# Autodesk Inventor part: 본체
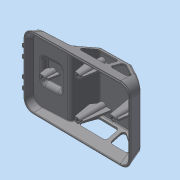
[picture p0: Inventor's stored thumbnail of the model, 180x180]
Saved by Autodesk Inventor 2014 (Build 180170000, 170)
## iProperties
Created: 2015-05
Part Number: 본체
Material: 일반
Document SubType Name: Modeling
Designer: dgall
Density: 1 g/cm^3
Appearance: 기본값
Author: dgall
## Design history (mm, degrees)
sketch "스케치1"
  geometry: L1 (-61, 0)-(61, 0); L2 (-61, 0)-(-61, 9); L3 (-61, 0)-(-58.588, 9); L4 (-61, 9)-(-19, 9); L5 (61, 0)-(31, 0); L6 (31, 0)-(31, 31); L7 (31, 31)-(57.056, 14.718); L8 (61, 0)-(57.056, 14.718); L9 (31, 31)-(-4.605, 31); L10 (-60, -1)-(60, -1); L11 (60, -1)-(60, 0); L12 (-61, 0)-(-60, 0); L13 (-60, 0)-(-60, -1); L14 (-4.605, 31)-(-18.633, 11.094); L15 (-58.588, 9)-(-18.633, 11.094); 2 further points
  constraints: 30 end point, 5 perpendicular, 4 point on line, 1 coincident, 1 horizontal, 1 midpoint, 1 parallel
  dimensions: "d0" = 122 distance of L1.start L1.end; "d3" = 9 distance of L1.start L2.end; "d4" = 75 deg angle of L1 L3; "d6" = 42 distance of L2.end L4.end; "d9" = 30 distance of L1.end L5.end; "d10" = 31 distance of L5.end L6.end; "d12" = 105 deg angle of L1 L8; "d13" = 35.60485 distance of L6.end L9.end; "d16" = 1 distance of L10.end L11.end; "d17" = 1 distance of L1.end L11.end; "d18" = 1 distance of L1.start L12.end; "d19" = 1 distance of L10.start L12.end; "d23" = 24.35241 distance of L9.end L14.end; "d24" = 30.72498 distance of L6.end L7.end; "d25" = 3 deg angle of L4 L15
extrude "돌출2" new body sketch "스케치1" stored distance "d26" = 76; taper "d27" = 0 deg
sketch "스케치2"
  geometry: L1 (0, 76)-(0, 0) reference; L2 (58.037, 38)-(0, 38); L3 (0, 38)-(11, 38); L4 (11, 51)-(11, 25); L5 (11, 51)-(31, 51); L6 (31, 51)-(31, 25); L7 (31, 25)-(11, 25)
  constraints: 12 end point, 3 perpendicular, 2 midpoint, 1 horizontal alignment, 1 point on line
  dimensions: "d29" = 26 distance of L4.start L4.end; "d30" = 11 distance of L2.end L3.end; "d31" = 20 distance of L4.start L5.end; "d32" = 26 distance of L5.end L6.end
extrude "돌출3" join sketch "스케치2" distance "d33" = 5; taper "d34" = 0 deg
fillet "모깎기1" dims "d72" = 3
fillet "모깎기2" dims "d73" = 2.5
sketch "스케치7"
  geometry: L1 (61.661, 76)-(61.661, 0) reference; L2 (65.605, 0)-(61.661, 0) reference; L3 (65.605, 76)-(65.605, 0) reference; L4 (61.661, 76)-(65.605, 76) reference; 3 further points
  constraints: 1 horizontal alignment, 1 midpoint, 1 other
  dimensions: "d74" = 50 distance from line of L3 point (15.605, 38)
  node "투영된 루프3"
feature "면 기울기3" dims angle "d139" = 15 deg
feature "면 기울기4" dims angle "d140" = 15 deg
fillet "모깎기7" dims "d141" = 12
fillet "모깎기8" dims "d142" = 3
fillet "모깎기9" dims "d143" = 2.5
feature "쉘2" dims "d144" = 2
sketch "스케치26"
  geometry: L1 (-3.049, 31)-(30.14, 31) reference; L2 (-17.793, 12.285)-(-5.501, 29.728) reference; L3 (31.73, 30.544)-(45.466, 21.961) reference; L4 (45.466, 21.961)-(56.054, 15.344) reference; L5 (-0.456, 26)-(18.418, 26); L6 (-2.908, 24.728)-(-9.25, 15.728); L7 (-6.798, 11)-(18.418, 11); L8 (21.418, 14)-(21.418, 23); L9 (25.571, 23)-(25.571, 14); L10 (30.296, 25.544)-(44.699, 16.544); L11 (28.571, 11)-(43.109, 11); L12 (28.571, 26)-(28.706, 26); A1 r 3 centre (18.418, 23) between (21.418, 23) and (18.418, 26); A2 r 3 centre (18.418, 14) between (18.418, 11) and (21.418, 14); A3 r 3 centre (-6.798, 14) between (-9.25, 15.728) and (-6.798, 11); A4 r 3 centre (28.571, 23) between (28.571, 26) and (25.571, 23); A5 r 3 centre (28.706, 23) between (30.296, 25.544) and (28.706, 26); A6 r 3 centre (28.571, 14) between (25.571, 14) and (28.571, 11); A7 r 3 centre (43.109, 14) between (43.109, 11) and (44.699, 16.544); A8 r 3 centre (-0.456, 23) between (-0.456, 26) and (-2.908, 24.728); 7 further points
  constraints: 16 end point, 16 point on circle, 16 tangent, 12 point on line, 8 centre point, 6 parallel, 5 equal radius, 2 perpendicular, 1 horizontal alignment
  dimensions: "d145" = 5 distance between parallel lines of L5 L1; "d147" = 5 distance between parallel lines of L2 L6; "d148" = 34 distance of point (-12.582, 11) point (21.418, 11); "d149" = 15 distance of point (21.418, 11) point (21.418, 26); "d150" = 3 radius of A1; "d151" = 5 distance between parallel lines of L10 L4; "d152" = 28 distance of point (25.571, 11) point (53.571, 11); "d153" = 15 distance of point (25.571, 26) point (25.571, 11); "d154" = 3 radius of A4; "d155" = 3 radius of A8
extrude "돌출12" cut sketch "스케치26" stored distance "d156" = 130; taper "d157" = 0 deg
feature "엠보싱2" dims "d158" = 0.5, "d159" = 0
sketch "스케치27"
  geometry: L1 (31, 30.583)-(31, -30.583) reference; L2 (29, 30.583)-(29, -30.583) reference; L3 (29, 22)-(29, -22); L4 (0, -28.811)-(0, 28.811) reference; L5 (29, 22)-(0, 22); L6 (29, -22)-(0, -22); L7 (0, 22)-(0, 25); L8 (0, 25)-(29, 26.013); L9 (29, 26.013)-(29, 22); L10 (0, -22)-(0, -25); L11 (0, -25)-(29, -26.013); L12 (29, -26.013)-(29, -22); 2 further points
  constraints: 18 end point, 6 point on line, 3 collinear, 2 midpoint, 2 perpendicular
  dimensions: "d160" = 44 distance of L3.start L3.end; "d161" = 3 distance of L5.end L7.end; "d162" = 2 deg angle of L5 L8; "d163" = 3 distance of L6.end L10.end; "d164" = 2 deg angle of L6 L11
revolve "회전3" stored, may be unused: angle "d165" = 90 deg
revolve "회전4" stored, may be unused: angle "d166" = 90 deg
sketch "스케치28"
  geometry: L1 (-44.765, 12.729)-(-30.784, 13.461) reference; L2 (-3.049, 29)-(-3.049, 29) reference; L3 (-3.866, 28.576)-(-3.866, 28.576) reference; L4 (-3, 0)-(3, 0) reference; L5 (0, 0)-(-40, 0); L6 (-40, 0)-(-40, 12.978); L7 (-40, 0)-(-37, 0); L8 (-37, 0)-(-36.54, 13.16); L9 (-36.54, 13.16)-(-40, 12.978)
  constraints: 10 end point, 3 point on line, 2 collinear, 1 perpendicular, 2 other
  dimensions: "d167" = 40 distance of L5.start L5.end; "d168" = 3 distance of L5.end L7.end; "d169" = 2 deg angle of L6 L8
revolve "회전5" sketch "스케치28" stored, may be unused: angle "d170" = 90 deg
sketch "스케치29"
  geometry: L1 (-3.049, 29)-(-3.049, 29) reference; L2 (-3.866, 28.576)-(-3.866, 28.576) reference; L3 (-3, 0)-(3, 0) reference; L4 (31.73, 30.544)-(45.466, 21.961) reference; L5 (30.67, 28.848)-(44.406, 20.265) reference; L6 (44.406, 20.265)-(54.994, 13.648) reference; L7 (0, 0)-(40, 0); L8 (40, 0)-(40, 23.018); L9 (40, 0)-(37, 0); L10 (37, 0)-(36.111, 25.448)
  constraints: 8 end point, 4 point on line, 1 perpendicular, 2 other
  dimensions: "d171" = 40 distance of L7.start L7.end; "d172" = 3 distance of L7.end L9.end; "d173" = 2 deg angle of L8 L10
revolve "회전6" sketch "스케치29" stored, may be unused: angle "d174" = 90 deg
sketch "스케치31"
  geometry: L1 (31.73, 30.544)-(45.466, 21.961) reference; L2 (39.886, 25.448)-(43.898, 22.94); L3 (39.886, 25.448)-(39.886, 25.448) reference; L4 (39.886, 25.448)-(39.886, 25.448) reference; L5 (39.886, 25.448)-(43.898, 25.448); L6 (43.898, 25.448)-(43.898, 22.94); 1 further point
  constraints: 6 end point, 2 point on line, 1 collinear, 1 horizontal, 1 perpendicular
  dimensions: "d176" = 2.50743 distance of L5.end L2.end
extrude "돌출13" cut sketch "스케치31" stored distance "d177" = 130; taper "d178" = 0 deg
sketch "스케치32"
  geometry: C1 r 3 at (0, 0) reference; C2 r 3 at (40, 22) reference; C3 r 3 at (80, 0) reference; C4 r 3 at (40, -22) reference; 1 further point
hole "구멍1" sketch "스케치32" at (0, 0), (40, -22), (80, 0), (40, 22) diameter "d179" = 3.302; stored, may be unused: countersink angle "d183" = 90 deg, drill point angle "d185" = 118 deg; dims "d180" = 9, "d181" = 4, "d182" = 2, "d184" = 11
sketch "스케치33"
  geometry: L1 (43.723, 20.692)-(36.111, 25.448) reference; L2 (43, 0)-(37, 0) reference; L3 (-36.54, 13.16)-(-43.447, 12.798) reference; L4 (-43, 0)-(-37, 0) reference; L5 (-36.54, 13.16)-(-37, 0) reference; L6 (-43.447, 12.798)-(-43, 0) reference; L7 (37, 0)-(36.111, 25.448) reference; L8 (43, 0)-(43.723, 20.692) reference; L9 (43, 0)-(43, 0); L10 (35, 2)-(37.788, 2); L11 (42.212, 2)-(45, 2); L12 (44.406, 20.265)-(54.994, 13.648) reference; L13 (45, 2)-(47.842, 18.118); L14 (35, 2)-(30.24, 28.995); L15 (42.212, 2)-(37.788, 2); L16 (40, 23.018)-(40, 0); L17 (-3.049, 29)-(30.14, 29) reference; L18 (-45, 2)-(-42.126, 2); L19 (-37.707, 2)-(-35, 2); L20 (-42.126, 2)-(-37.707, 2); L21 (-35, 2)-(-33, 13.345); L22 (-40, 12.978)-(-40, 0); L23 (-45, 2)-(-45.287, 12.701); L24 (-42.126, 2)-(-42.126, 12.867); L25 (-42.126, 12.867)-(-45.287, 12.701); L26 (42.212, 2)-(42.212, 21.636); L27 (42.212, 21.636)-(47.842, 18.118); L28 (37.788, 2)-(37.788, 24.4); L29 (37.788, 24.4)-(30.67, 28.848); L30 (-37.707, 2)-(-37.707, 13.098); L31 (-33, 13.345)-(-37.707, 13.098); A1 r 1 centre (30.14, 28) between (30.67, 28.848) and (30.14, 29) reference; A2 r 0.5 centre (-45.261, 12.202) between (-45.287, 12.701) and (-45.76, 12.221) reference; A3 r 1 centre (30.14, 28) between (30.67, 28.848) and (30.24, 28.995); 6 further points; 1 other entity
  constraints: 42 end point, 8 parallel, 3 midpoint, 3 point on circle, 2 perpendicular, 2 point on line, 2 tangent, 2 vertical alignment, 1 centre point, 1 coincident, 1 collinear, 1 concentric, 12 other
  dimensions: "d189" = 10 distance of L10.start L11.end; "d190" = 2 horizontal distance of L8.start L11.end; "d191" = 2 horizontal distance of L2.end L10.start; "d193" = 10 deg angle of L16 L14; "d194" = 10 deg angle of L13 L16; "d195" = 2 horizontal distance of L9.end L11.end; "d196" = 2 horizontal distance of L2.end L10.start; "d197" = 10 distance of L18.start L19.end; "d198" = 2 horizontal distance of L4.end L19.end; "d199" = 2 horizontal distance of L4.start L18.start; "d200" = 10 deg angle of L22 L21; "d201" = 2 horizontal distance of L4.end L19.end; "d202" = 10.8669 distance of L18.end L24.end; "d203" = 22.39984 distance of L10.end L28.end; "d204" = 19.6358 distance of L11.start L26.end
  node "투영된 루프15"
  node "투영된 루프16"
extrude "돌출14" join sketch "스케치33" stored distance "d206" = 2; taper "d207" = 0 deg
node "작업 평면5"
sketch "스케치35"
  geometry: L1 (-3.866, 28.576)-(-3.866, 28.576) reference; L2 (-3.049, 29)-(-3.049, 29) reference; L3 (3, 0)-(-3, 0) reference; L4 (3, 0)-(4.013, 29) reference; L5 (-3, 0)-(-3.992, 28.398) reference; L6 (4.013, 29)-(-3.049, 29) reference; L7 (-3.049, 29)-(30.14, 29) reference; L8 (-16.159, 11.133)-(-3.866, 28.576) reference; L9 (5, 2)-(9.761, 29); L10 (2.167, 29)-(9.761, 29); L11 (0, 29)-(0, 0); L12 (-4.809, 2)-(-2.082, 2); L13 (2.167, 2)-(5, 2); L14 (2.167, 29)-(2.167, 2); L15 (-4.809, 2)-(-8.368, 22.188); L16 (-2.082, 2)-(-2.082, 29); L17 (-8.368, 22.188)-(-3.992, 28.398); L18 (-2.082, 29)-(-3.049, 29); L19 (-3.992, 28.398)-(-3.049, 29); 2 further points
  constraints: 22 end point, 5 point on line, 3 collinear, 3 perpendicular, 2 parallel, 1 midpoint, 1 vertical alignment, 2 other
  dimensions: "d211" = 2 horizontal distance of L3.start L9.start; "d213" = 10 deg angle of L11 L9; "d214" = 2 vertical distance of L3.end L12.start; "d215" = 2.16705 distance of L10.start L11.start; "d216" = 7.59378 distance of L10.start L9.end; "d217" = 10 deg angle of L11 L15; "d218" = 2.08199 distance of L11.start L16.end; "d219" = 7.59756 distance of L15.end L5.end
extrude "돌출15" join sketch "스케치35" stored distance "d220" = 2; taper "d221" = 0 deg
node "작업 평면6"
sketch "스케치36"
  geometry: L1 (-3.049, 29)-(-3.049, 29) reference; L2 (-3.866, 28.576)-(-3.866, 28.576) reference; L3 (-3, 0)-(3, 0) reference; L4 (4.013, 29)-(3, 0) reference; L5 (-3.992, 28.398)-(-3, 0) reference; L6 (-3.049, 29)-(30.14, 29) reference; L7 (-16.159, 11.133)-(-3.866, 28.576) reference; L8 (-4.929, 2)-(-2.2, 2); L9 (2.189, 2)-(5.071, 2); L10 (0, 0)-(0, 29); L11 (2.189, 2)-(2.189, 29); L12 (5.071, 2)-(9.832, 29); L13 (9.832, 29)-(2.189, 29); L14 (-2.2, 2)-(-2.2, 29); L15 (-4.929, 2)-(-8.465, 22.051); L16 (-8.465, 22.051)-(-3.992, 28.398); L17 (-2.2, 29)-(-3.049, 29); 2 further points
  constraints: 20 end point, 5 point on line, 4 perpendicular, 2 collinear, 2 horizontal, 1 midpoint, 1 vertical alignment, 2 other
  dimensions: "d223" = 10 distance of L8.start L9.end; "d224" = 2 vertical distance of point (0, 0) L9.end; "d225" = 2 vertical distance of L3.start L8.start; "d226" = 10 deg angle of L11 L12; "d227" = 2 distance from line of L4 L9.end; "d228" = 7.64307 distance of L12.end L11.end; "d229" = 10 deg angle of L10 L15; "d230" = 0.84861 distance of L1.end L14.end
extrude "돌출16" join sketch "스케치36" stored distance "d231" = 2; taper "d232" = 0 deg
sketch "스케치38"
  geometry: L1 (-36.54, 13.16)-(-43.447, 12.798) reference; L2 (-43, 0)-(-37, 0) reference; L3 (-36.54, 13.16)-(-37, 0) reference; L4 (-43.447, 12.798)-(-43, 0) reference; L5 (-44.929, 2)-(-42.066, 2); L6 (-37.856, 2)-(-34.929, 2); L7 (-39.994, 12.979)-(-40, 0); L8 (-37.856, 2)-(-37.85, 13.091); L9 (-44.765, 12.729)-(-30.784, 13.461) reference; L10 (-34.929, 2)-(-32.922, 13.349); L11 (-32.922, 13.349)-(-37.85, 13.091); L12 (-42.066, 2)-(-42.061, 12.87); L13 (-44.929, 2)-(-46.346, 10.059); L14 (-42.061, 12.87)-(-45.287, 12.701); A1 r 5 centre (-50.756, 12.415) between (-50.495, 7.421) and (-45.76, 12.221) reference; A2 r 0.5 centre (-45.261, 12.202) between (-45.287, 12.701) and (-45.76, 12.221) reference; 2 further points
  constraints: 18 end point, 4 parallel, 3 point on line, 2 collinear, 2 midpoint, 1 point on circle, 1 tangent, 1 vertical alignment
  dimensions: "d233" = 10 distance of L5.start L6.end; "d234" = 2 vertical distance of L2.end L6.end; "d235" = 2 vertical distance of L2.start L5.start; "d236" = 10 deg angle of L7 L10; "d237" = 2 distance from line of L3 L6.end; "d238" = 4.92806 horizontal distance of L10.end L8.end; "d239" = 10 deg angle of L7 L13; "d240" = 4.21066 horizontal distance of L12.end L8.end
extrude "돌출17" join sketch "스케치38" stored distance "d241" = 2; taper "d242" = 0 deg
sketch "스케치39"
  geometry: L1 (-110.406, 68.806)-(-11.866, 70.189) reference; L2 (-2.071, 60.531)-(-2.071, 0.141) reference; L3 (-11.866, -9.518)-(-110.406, -8.134) reference; L4 (-119.929, 1.524)-(-119.929, 59.147) reference; L5 (0, 0)-(0, 60.672) reference; L6 (-110.572, 70.874)-(-11.754, 72.262) reference; L7 (-122, 59.284)-(-122, 1.388) reference; L8 (-11.754, -11.59)-(-110.572, -10.202) reference; L9 (-1, 60.672)-(-1, 0); L10 (-11.74, -10.59)-(-110.558, -9.202); L11 (-121, 1.388)-(-121, 59.284); L12 (-110.558, 69.874)-(-11.74, 71.262); 9 further points; 8 other entities
  constraints: 8 end point, 7 parallel, 20 other
  dimensions: "d243" = 1 distance between parallel lines of L12 L6
extrude "돌출18" join sketch "스케치39" distance "d244" = 1; taper "d245" = 0 deg
node "작업 평면7"
sketch "스케치40"
  geometry: L1 (0, -10)-(0, 10); L2 (0, 10)-(0, 21); L3 (0, -10)-(0, -21); L4 (0, -21)-(0, -26.309); L5 (0, 21)-(0, 25.078); L6 (0, -23)-(0, -19); L7 (0, -23)-(0, -19); L8 (0, -12)-(0, -8); L9 (0, 8)-(0, 12); L10 (0, 19)-(0, 23); A1 r 2 centre (0, -21) between (0, -23) and (0, -19); A2 r 2 centre (0, -10) between (0, -12) and (0, -8); A3 r 2 centre (0, 10) between (0, 8) and (0, 12); A4 r 2 centre (0, 21) between (0, 19) and (0, 23); 2 further points
  constraints: 20 end point, 9 collinear, 8 point on circle, 8 point on line, 5 coincident, 4 centre point, 1 midpoint, 1 vertical
  dimensions: "d247" = 20 distance of L1.start L1.end; "d248" = 11 distance of L1.end L2.end; "d249" = 11 distance of L1.start L3.end; "d250" = 4 diameter of A1; "d251" = 4 diameter of A2; "d252" = 4 diameter of A3; "d253" = 4 diameter of A4
extrude "돌출19" join sketch "스케치40" distance "d254" = 2; taper "d255" = 0 deg
extrude "돌출20" join sketch "스케치40" distance "d256" = 2; taper "d257" = 0 deg
chamfer "모따기1" distance "d258" = 0.5; stored, may be unused: second distance "d259" = 2, angle "d260" = 45 deg
sketch "스케치8"
  geometry: L1 (14.718, -38)-(14.718, 38) reference; L2 (0, 38)-(14.718, 38) reference; L3 (0, -38)-(0, 38) reference; L4 (14.718, -38)-(0, -38) reference; L5 (-1, -37)-(-1, 37); L6 (-1, -37)-(0, -37); L7 (-1, 37)-(0, 37); 3 further points
  constraints: 6 end point, 2 midpoint, 2 perpendicular, 2 point on line, 1 horizontal alignment, 1 parallel
  dimensions: "d77" = 74 distance of L5.start L5.end; "d78" = 1 horizontal distance of L5.end L2.start
extrude "돌출6" join sketch "스케치8" stored distance "d79" = 120; taper "d80" = 0 deg
sketch "스케치10"
  geometry: L1 (-44.869, 14.726)-(-30.889, 15.459) reference; L2 (-45.287, 12.701)-(-30.262, 13.489); L3 (-50.495, 7.421)-(-24.53, 8.782); A1 r 2.5 centre (-30.236, 12.989) between (-27.761, 13.347) and (-30.366, 15.486) reference; A2 r 3 centre (-50.756, 12.415) between (-50.599, 9.419) and (-47.759, 12.299) reference; A3 r 2.5 centre (-45.261, 12.202) between (-45.391, 14.698) and (-47.759, 12.299) reference; A4 r 3 centre (-24.792, 13.775) between (-27.761, 13.347) and (-24.635, 10.779) reference; A5 r 0.5 centre (-30.236, 12.989) between (-29.741, 13.061) and (-30.262, 13.489); A6 r 5 centre (-24.792, 13.775) between (-29.741, 13.061) and (-24.53, 8.782); A7 r 5 centre (-50.756, 12.415) between (-50.495, 7.421) and (-45.76, 12.221); A8 r 0.5 centre (-45.261, 12.202) between (-45.287, 12.701) and (-45.76, 12.221); 1 further point
  constraints: 8 point on circle, 4 centre point, 4 end point, 2 tangent, 1 parallel, 2 other
  dimensions: "d91" = 2 radial gap between concentric circles of A4 A6; "d93" = 2 radial gap between concentric circles of A2 A7; "d94" = 2 distance between parallel lines of L2 L1
extrude "돌출8" cut sketch "스케치10" stored distance "d95" = 22; taper "d96" = 0 deg
feature "면 기울기1" dims angle "d112" = 15 deg
feature "면 기울기2" dims angle "d113" = 15 deg
sketch "스케치19"
  geometry: L1 (-18.633, 11.094)-(-4.605, 31) reference; L2 (-4.605, 31)-(31, 31) reference; L3 (31, 31)-(57.056, 14.718) reference; L4 (57.056, 14.718)-(61, 0) reference; L5 (-2.908, 24.728)-(-9.25, 15.728); L6 (-0.456, 26)-(18.418, 26); L7 (-6.798, 11)-(18.418, 11); L8 (21.418, 14)-(21.418, 23); L9 (25.571, 23)-(25.571, 14); L10 (30.296, 25.544)-(44.699, 16.544); L11 (28.571, 26)-(28.706, 26); L12 (28.571, 11)-(43.109, 11); A1 r 3 centre (18.418, 23) between (21.418, 23) and (18.418, 26); A2 r 3 centre (18.418, 14) between (18.418, 11) and (21.418, 14); A3 r 3 centre (-6.798, 14) between (-9.25, 15.728) and (-6.798, 11); A4 r 3 centre (-0.456, 23) between (-0.456, 26) and (-2.908, 24.728); A5 r 3 centre (28.571, 23) between (28.571, 26) and (25.571, 23); A6 r 3 centre (28.706, 23) between (30.296, 25.544) and (28.706, 26); A7 r 3 centre (28.571, 14) between (25.571, 14) and (28.571, 11); A8 r 3 centre (43.109, 14) between (43.109, 11) and (44.699, 16.544); 6 further points
  constraints: 16 end point, 16 point on circle, 16 tangent, 10 point on line, 8 centre point, 6 equal radius, 6 parallel, 2 perpendicular, 1 horizontal alignment
  dimensions: "d114" = 5 distance between parallel lines of L1 L5; "d115" = 5 distance between parallel lines of L6 L2; "d116" = 15 distance of point (21.418, 11) point (21.418, 26); "d117" = 34 distance of point (21.418, 11) point (-12.582, 11); "d118" = 3 radius of A1; "d119" = 5 distance between parallel lines of L10 L3; "d120" = 5 distance between parallel lines of L11 L2; "d121" = 28 distance of point (53.571, 11) point (25.571, 11); "d122" = 3 radius of A5
extrude "돌출10" cut sketch "스케치19" stored distance "d123" = 130; taper "d124" = 0 deg
node "솔리드2"
node "투영된 루프4"
node "투영된 루프10"
node "투영된 루프11"
node "투영된 루프12"
node "투영된 루프13"
node "투영된 루프14"
node "투영된 루프18"
node "투영된 루프19"
node "투영된 루프20"
other parameters: "d208" = 22, "d222" = -22, "d246" = -61
